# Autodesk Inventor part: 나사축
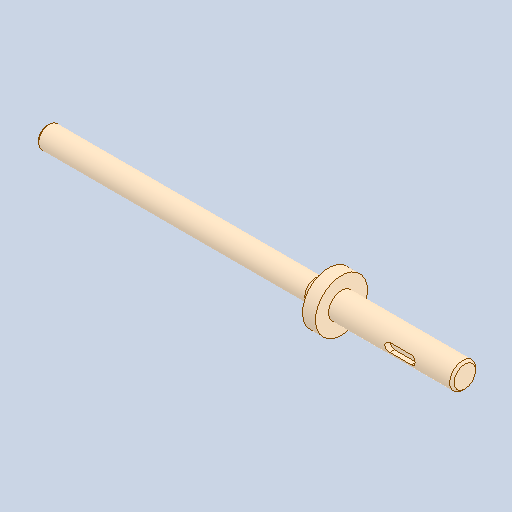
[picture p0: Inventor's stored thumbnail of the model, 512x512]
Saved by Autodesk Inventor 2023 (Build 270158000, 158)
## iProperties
Created: 2024-07
Part Number: 나사축
Material: 강철, 연강
Document SubType Name: Modeling
Designer: home
Density: 7.86 g/cm^3
Appearance: 기본값
Author: jhkim
Sending System: Autodesk Inventor 2025
Preprocessor: ST-DEVELOPER v20
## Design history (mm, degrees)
feature "솔리드1"
node "솔리드2"
